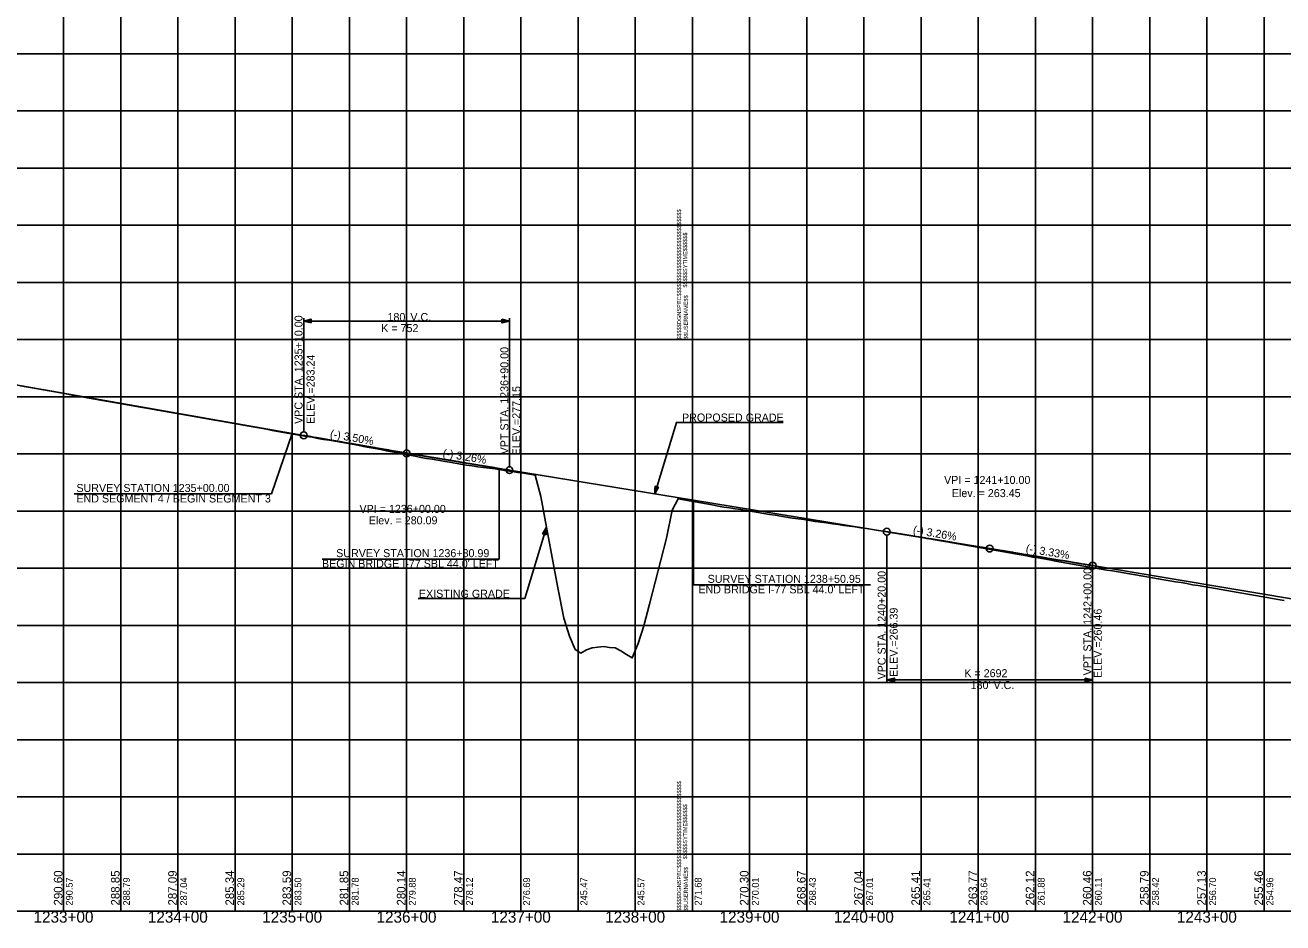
# Model space of a CAD drawing. Extents: x -90830 to 2015517, y -20856 to 836331.
# Drawn here: x 12190 to 13290, y -10807 to -10022 of the extents above; entities that cross this region are included whole.
import ezdxf

# ---------------------------------------------------------------- set-up
doc = ezdxf.new("R2010")
doc.units = 0
for name, color, linetype in [('Level 1', 7, 'Continuous'), ('RD_DDB_GradeTX', 7, 'Continuous'), ('RD_DDB_Profile_Elev', 7, 'Continuous'), ('RD_DDB_Profile_EX', 7, 'Continuous'), ('RD_DDB_Profile_Lbl', 7, 'Continuous'), ('RD_DDB_Profile_PR', 7, 'Continuous'), ('RD_DDB_StaTX', 7, 'Continuous'), ('RD_DDB_StripGrade', 7, 'Continuous'), ('RD_DDB_VCLbl', 7, 'Continuous'), ('RD_GPK_Profile_Cell', 7, 'Continuous'), ('RD_PD_Final_TX', 7, 'Continuous'), ('RD_TX_Drainage', 7, 'Continuous')]:
    doc.layers.add(name, color=color, linetype=linetype)

msp = doc.modelspace()

# ---------------------------------------------------------------- linework, layer by layer
at = {"layer": 'Level 1'}
for p, q in [((12223.5, -9797.1), (12223.5, -10297.1)), ((12273.5, -9797.1), (12273.5, -10297.1)), ((12323.5, -9797.1), (12323.5, -10297.1)), ((12373.5, -9797.1), (12373.5, -10297.1)), ((12423.5, -9797.1), (12423.5, -10297.1)), ((12473.5, -9797.1), (12473.5, -10297.1)), ((12523.5, -9797.1), (12523.5, -10297.1)), ((12573.5, -9797.1), (12573.5, -10297.1)), ((12623.5, -9797.1), (12623.5, -10297.1)), ((12673.5, -9797.1), (12673.5, -10297.1)), ((12723.5, -9797.1), (12723.5, -10297.1)), ((12773.5, -9797.1), (12773.5, -10297.1)), ((12773.5, -9797.1), (12773.5, -10297.1)), ((12773.5, -9797.1), (12773.5, -10297.1)), ((12823.5, -9797.1), (12823.5, -10297.1)), ((12873.5, -9797.1), (12873.5, -10297.1)), ((12923.5, -9797.1), (12923.5, -10297.1)), ((12973.5, -9797.1), (12973.5, -10297.1)), ((13023.5, -9797.1), (13023.5, -10297.1)), ((13073.5, -9797.1), (13073.5, -10297.1)), ((13123.5, -9797.1), (13123.5, -10297.1)), ((13173.5, -9797.1), (13173.5, -10297.1)), ((13223.5, -9797.1), (13223.5, -10297.1)), ((13273.5, -9797.1), (13273.5, -10297.1)), ((11173.5, -10047.1), (12773.5, -10047.1)), ((12773.5, -10047.1), (14373.5, -10047.1)), ((11173.5, -10097.1), (12773.5, -10097.1)), ((12773.5, -10097.1), (14373.5, -10097.1)), ((11173.5, -10147.1), (12773.5, -10147.1)), ((12773.5, -10147.1), (14373.5, -10147.1)), ((11173.5, -10197.1), (12773.5, -10197.1)), ((12773.5, -10197.1), (14373.5, -10197.1)), ((11173.5, -10247.1), (12773.5, -10247.1)), ((12773.5, -10247.1), (14373.5, -10247.1)), ((11173.5, -10297.1), (12773.5, -10297.1)), ((11173.5, -10297.1), (12773.5, -10297.1)), ((12223.5, -10297.1), (12223.5, -10797.1)), ((12273.5, -10297.1), (12273.5, -10797.1)), ((12323.5, -10297.1), (12323.5, -10797.1)), ((12373.5, -10297.1), (12373.5, -10797.1)), ((12423.5, -10297.1), (12423.5, -10797.1)), ((12473.5, -10297.1), (12473.5, -10797.1)), ((12523.5, -10297.1), (12523.5, -10797.1)), ((12573.5, -10297.1), (12573.5, -10797.1)), ((12623.5, -10297.1), (12623.5, -10797.1)), ((12673.5, -10297.1), (12673.5, -10797.1)), ((12723.5, -10297.1), (12723.5, -10797.1)), ((12773.5, -10297.1), (14373.5, -10297.1)), ((12773.5, -10297.1), (12773.5, -10797.1)), ((12773.5, -10297.1), (12773.5, -10797.1)), ((12773.5, -10297.1), (14373.5, -10297.1)), ((12773.5, -10297.1), (12773.5, -10797.1)), ((12823.5, -10297.1), (12823.5, -10797.1)), ((12873.5, -10297.1), (12873.5, -10797.1)), ((12923.5, -10297.1), (12923.5, -10797.1)), ((12973.5, -10297.1), (12973.5, -10797.1)), ((13023.5, -10297.1), (13023.5, -10797.1)), ((13073.5, -10297.1), (13073.5, -10797.1)), ((13123.5, -10297.1), (13123.5, -10797.1)), ((13173.5, -10297.1), (13173.5, -10797.1)), ((13223.5, -10297.1), (13223.5, -10797.1)), ((13273.5, -10297.1), (13273.5, -10797.1)), ((11173.5, -10347.1), (12773.5, -10347.1)), ((12773.5, -10347.1), (14373.5, -10347.1)), ((11173.5, -10397.1), (12773.5, -10397.1)), ((12773.5, -10397.1), (14373.5, -10397.1)), ((11173.5, -10447.1), (12773.5, -10447.1)), ((12773.5, -10447.1), (14373.5, -10447.1)), ((11173.5, -10497.1), (12773.5, -10497.1)), ((12773.5, -10497.1), (14373.5, -10497.1)), ((11173.5, -10547.1), (12773.5, -10547.1)), ((12773.5, -10547.1), (14373.5, -10547.1)), ((11173.5, -10597.1), (12773.5, -10597.1)), ((12773.5, -10597.1), (14373.5, -10597.1)), ((11173.5, -10647.1), (12773.5, -10647.1)), ((12773.5, -10647.1), (14373.5, -10647.1)), ((11173.5, -10697.1), (12773.5, -10697.1)), ((12773.5, -10697.1), (14373.5, -10697.1)), ((11173.5, -10747.1), (12773.5, -10747.1)), ((12773.5, -10747.1), (14373.5, -10747.1)), ((11173.5, -10797.1), (12773.5, -10797.1)), ((12773.5, -10797.1), (14373.5, -10797.1))]:
    msp.add_line(p, q, dxfattribs=at)
at = {"layer": 'RD_DDB_GradeTX'}
for p, q in [((12453.5, -10384.4), (12520.5, -10396.1)), ((12593.5, -10408.1), (12526.4, -10397.1)), ((12963.4, -10468.4), (13030.5, -10479.4)), ((13103.5, -10491.5), (13036.4, -10480.3))]:
    msp.add_line(p, q, dxfattribs=at)
for centre in [(12523.5, -10396.7), (13033.5, -10479.9)]:
    msp.add_circle(centre, 3, dxfattribs=at)
at = {"layer": 'RD_DDB_Profile_EX'}
for points in [[(12185.9, -10337.5), (12190.9, -10338.4), (12195.9, -10339.3), (12200.9, -10340.2), (12205.9, -10341.1), (12210.9, -10342), (12215.9, -10342.9), (12220.9, -10343.8), (12225.9, -10344.7), (12230.9, -10345.6), (12235.9, -10346.5), (12240.9, -10347.4), (12245.9, -10348.3), (12250.9, -10349.2), (12255.9, -10350.1), (12260.9, -10351), (12265.9, -10351.8), (12270.9, -10352.7), (12275.9, -10353.6), (12280.9, -10354.5), (12285.9, -10355.3), (12290.9, -10356.2), (12295.9, -10357.1), (12300.9, -10358), (12305.9, -10358.9), (12310.9, -10359.7), (12315.9, -10360.6), (12320.9, -10361.5), (12325.9, -10362.3), (12330.9, -10363.2), (12335.9, -10364.1), (12340.9, -10364.9), (12345.9, -10365.8), (12350.9, -10366.7), (12355.9, -10367.5), (12360.9, -10368.4), (12365.9, -10369.3), (12370.9, -10370.2), (12375.9, -10371.1), (12380.9, -10372), (12385.9, -10372.9), (12390.9, -10373.8), (12395.9, -10374.7), (12400.9, -10375.6), (12405.9, -10376.5), (12410.9, -10377.4), (12415.9, -10378.3), (12420.9, -10379.2), (12425.9, -10380), (12430.9, -10380.9), (12435.9, -10381.8), (12440.9, -10382.6), (12445.9, -10383.5), (12450.9, -10384.4), (12455.9, -10385.2), (12460.9, -10386.1), (12465.9, -10386.9), (12470.9, -10387.8), (12475.9, -10388.7), (12480.9, -10389.6), (12485.9, -10390.5), (12490.9, -10391.4), (12495.9, -10392.3), (12500.9, -10393.3), (12505.9, -10394.3), (12510.9, -10395.3), (12515.9, -10396.3), (12520.9, -10397.2), (12525.9, -10398.2), (12530.9, -10399.2), (12535.9, -10400.2), (12540.9, -10401), (12545.9, -10401.8)], [(12545.9, -10401.8), (12550.9, -10402.7), (12555.9, -10403.5), (12560.9, -10404.3), (12565.9, -10405.2), (12570.9, -10406.1), (12575.9, -10406.9), (12580.9, -10407.6), (12585.9, -10408.3), (12590.9, -10409), (12595.9, -10409.7), (12600.9, -10410.3), (12605.9, -10411), (12610.9, -10411.8), (12615.9, -10412.5), (12620.9, -10413.3), (12625.9, -10414.1), (12630.9, -10414.9), (12635.9, -10415.7), (12640.9, -10434.5), (12645.9, -10461.2), (12650.9, -10487.8), (12655.9, -10514.3), (12660.9, -10540.8), (12665.9, -10556.6), (12670.9, -10568.3), (12675.9, -10571.3), (12680.9, -10568.5), (12685.9, -10566.6), (12690.9, -10566.1), (12695.9, -10565.7), (12700.9, -10566.3), (12705.9, -10566.8), (12710.9, -10569.4), (12715.9, -10572.5), (12720.9, -10575.6), (12725.9, -10562.9), (12730.9, -10547.5), (12735.9, -10528.4), (12740.9, -10509.2), (12745.9, -10490.1), (12750.9, -10470.9), (12755.9, -10446.4), (12760.9, -10436.5), (12765.9, -10437.4), (12770.9, -10438.3), (12775.9, -10439.1), (12780.9, -10440), (12785.9, -10440.9), (12790.9, -10441.8), (12795.9, -10442.8), (12800.9, -10443.6), (12805.9, -10444.3), (12810.9, -10445.1), (12815.9, -10445.8), (12820.9, -10446.6), (12825.9, -10447.5), (12830.9, -10448.3), (12835.9, -10449.2), (12840.9, -10450), (12845.9, -10450.8), (12850.9, -10451.6), (12855.9, -10452.4), (12860.9, -10453.2), (12865.9, -10453.9), (12870.9, -10454.6), (12875.9, -10455.4), (12880.9, -10456.1), (12885.9, -10456.8), (12890.9, -10457.5), (12895.9, -10458.2), (12900.9, -10458.9), (12905.9, -10459.6), (12910.9, -10460.3), (12915.9, -10461), (12920.9, -10461.7), (12925.9, -10462.5), (12930.9, -10463.2), (12935.9, -10464), (12940.9, -10464.7), (12945.9, -10465.5), (12950.9, -10466.3), (12955.9, -10467.1), (12960.9, -10467.9), (12965.9, -10468.8), (12970.9, -10469.6), (12975.9, -10470.5), (12980.9, -10471.4), (12985.9, -10472.2), (12990.9, -10473.1), (12995.9, -10474), (13000.9, -10474.9), (13005.9, -10475.8), (13010.9, -10476.7), (13015.9, -10477.6), (13020.9, -10478.5), (13025.9, -10479.4), (13030.9, -10480.2), (13035.9, -10481.1), (13040.9, -10482), (13045.9, -10482.9)], [(13045.9, -10482.9), (13050.9, -10483.7), (13055.9, -10484.6), (13060.9, -10485.5), (13065.9, -10486.4), (13070.9, -10487.3), (13075.9, -10488.1), (13080.9, -10489), (13085.9, -10489.9), (13090.9, -10490.8), (13095.9, -10491.7), (13100.9, -10492.6), (13105.9, -10493.5), (13110.9, -10494.4), (13115.9, -10495.3), (13120.9, -10496.1), (13125.9, -10497), (13130.9, -10497.8), (13135.9, -10498.7), (13140.9, -10499.5), (13145.9, -10500.4), (13150.9, -10501.2), (13155.9, -10502), (13160.9, -10502.9), (13165.9, -10503.8), (13170.9, -10504.6), (13175.9, -10505.5), (13180.9, -10506.3), (13185.9, -10507.2), (13190.9, -10508), (13195.9, -10508.9), (13200.9, -10509.7), (13205.9, -10510.6), (13210.9, -10511.5), (13215.9, -10512.3), (13220.9, -10513.2), (13225.9, -10514.1), (13230.9, -10514.9), (13235.9, -10515.8), (13240.9, -10516.7), (13245.9, -10517.6), (13250.9, -10518.4), (13255.9, -10519.3), (13260.9, -10520.2), (13265.9, -10521), (13270.9, -10521.9), (13275.9, -10522.7), (13280.9, -10523.6), (13285.9, -10524.4), (13290.9, -10525.2)]]:
    msp.add_lwpolyline(points, dxfattribs=at)
at = {"layer": 'RD_DDB_Profile_Lbl'}
for p, q in [((12423.5, -10379.2), (12405.2, -10432.1)), ((12604.4, -10489.3), (12604.4, -10409.9)), ((12232.7, -10432.1), (12405.2, -10432.1)), ((12774.4, -10511.5), (12774.4, -10437.6)), ((12449.8, -10489.3), (12604.4, -10489.3)), ((12774.4, -10511.5), (12929.1, -10511.5))]:
    msp.add_line(p, q, dxfattribs=at)
at = {"layer": 'RD_DDB_Profile_PR'}
for p, q in [((11473.4, -10212.8), (12433.5, -10380.9)), ((12613.5, -10411.3), (12774.4, -10437.6)), ((12774.4, -10437.6), (12943.5, -10465.2)), ((13123.5, -10494.8), (13336, -10530.2))]:
    msp.add_line(p, q, dxfattribs=at)
for points in [[(12433.5, -10380.9), (12437.1, -10381.5), (12440.7, -10382.2), (12444.3, -10382.8), (12447.9, -10383.4), (12451.5, -10384), (12455.1, -10384.7), (12458.7, -10385.3), (12462.3, -10385.9), (12465.9, -10386.5), (12469.5, -10387.2), (12473.1, -10387.8), (12476.7, -10388.4), (12480.3, -10389), (12483.9, -10389.6), (12487.5, -10390.3), (12491.1, -10390.9), (12494.7, -10391.5), (12498.3, -10392.1), (12501.9, -10392.7), (12505.5, -10393.3), (12509.1, -10394), (12512.7, -10394.6), (12516.3, -10395.2), (12519.9, -10395.8), (12523.5, -10396.4), (12527.1, -10397), (12530.7, -10397.6), (12534.3, -10398.2), (12537.9, -10398.8), (12541.5, -10399.4), (12545.1, -10400), (12548.7, -10400.6), (12552.3, -10401.2), (12555.9, -10401.8), (12559.5, -10402.4), (12563.1, -10403), (12566.7, -10403.6), (12570.3, -10404.2), (12573.9, -10404.8), (12577.5, -10405.4), (12581.1, -10406), (12584.7, -10406.6), (12588.3, -10407.2), (12591.9, -10407.8), (12595.5, -10408.4), (12599.1, -10409), (12602.7, -10409.6), (12604.4, -10409.9)], [(12604.4, -10409.9), (12606.3, -10410.2), (12609.9, -10410.8), (12613.5, -10411.3)], [(12943.5, -10465.2), (12947.1, -10465.8), (12950.7, -10466.4), (12954.3, -10466.9), (12957.9, -10467.5), (12961.5, -10468.1), (12965.1, -10468.7), (12968.7, -10469.3), (12972.3, -10469.9), (12975.9, -10470.5), (12979.5, -10471.1), (12983.1, -10471.6), (12986.7, -10472.2), (12990.3, -10472.8), (12993.9, -10473.4), (12997.5, -10474), (13001.1, -10474.6), (13004.7, -10475.2), (13008.3, -10475.8), (13011.9, -10476.4), (13015.5, -10477), (13019.1, -10477.6), (13022.7, -10478.2), (13026.3, -10478.7), (13029.9, -10479.3), (13033.5, -10479.9), (13037.1, -10480.5), (13040.7, -10481.1), (13044.3, -10481.7), (13047.9, -10482.3), (13051.5, -10482.9), (13055.1, -10483.5), (13058.7, -10484.1), (13062.3, -10484.7), (13065.9, -10485.3), (13069.5, -10485.9), (13073.1, -10486.5), (13076.7, -10487.1), (13080.3, -10487.7), (13083.9, -10488.3), (13087.5, -10488.9), (13091.1, -10489.5), (13094.7, -10490.1), (13098.3, -10490.6), (13101.9, -10491.2), (13105.5, -10491.8), (13109.1, -10492.4), (13112.7, -10493), (13116.3, -10493.6), (13119.9, -10494.2), (13123.5, -10494.8)]]:
    msp.add_spline(points, degree=3, dxfattribs=at)
at = {"layer": 'RD_DDB_VCLbl'}
for p, q in [((12433.5, -10278.4), (12433.5, -10377.9)), ((12433.5, -10280.9), (12613.5, -10280.9)), ((12613.5, -10278.4), (12613.5, -10408.3)), ((12943.5, -10597.3), (12943.5, -10468.2)), ((13123.5, -10597.3), (13123.5, -10497.8)), ((12943.5, -10594.8), (13123.5, -10594.8))]:
    msp.add_line(p, q, dxfattribs=at)
for centre in [(12433.5, -10380.9), (12613.5, -10411.3), (12943.5, -10465.2), (13123.5, -10494.8)]:
    msp.add_circle(centre, 3, dxfattribs=at)
at = {"layer": 'RD_GPK_Profile_Cell'}
msp.add_line((4823.5, -10797.1), (75223.5, -10797.1), dxfattribs=at)
at = {"layer": 'RD_PD_Final_TX'}
for p, q in [((12740.5, -10432), (12740.8, -10425.3)), ((12742.3, -10425.8), (12740.5, -10432)), ((12740.5, -10432), (12743.9, -10426.3)), ((12740.8, -10425.3), (12743.9, -10426.3)), ((12645.9, -10461.2), (12642.5, -10466.9)), ((12645.6, -10467.8), (12642.5, -10466.9)), ((12644.1, -10467.4), (12645.9, -10461.2)), ((12645.9, -10461.2), (12645.6, -10467.8))]:
    msp.add_line(p, q, dxfattribs=at)
for points in [[(12852.9, -10369.6), (12759.5, -10369.6), (12740.5, -10432)], [(12742.3, -10425.9), (12740.5, -10431.6), (12742.3, -10425.8), (12740.5, -10431.4), (12742.2, -10425.8), (12740.6, -10431.2), (12742.1, -10425.8), (12740.6, -10430.9), (12742, -10425.8), (12740.6, -10430.6), (12742, -10425.7), (12740.6, -10430.2), (12741.9, -10425.7), (12740.6, -10429.9), (12741.8, -10425.7), (12740.6, -10429.6), (12741.7, -10425.7), (12740.7, -10429.3), (12741.7, -10425.7), (12740.7, -10429), (12741.6, -10425.7), (12740.7, -10428.7), (12741.5, -10425.6), (12740.7, -10428.2), (12741.4, -10425.6), (12740.7, -10427.9), (12741.4, -10425.6), (12740.7, -10427.5), (12741.3, -10425.6), (12740.8, -10427.1), (12741.2, -10425.5), (12740.8, -10426.8), (12741.1, -10425.5), (12740.8, -10426.5), (12741.1, -10425.4), (12740.8, -10426.1), (12741, -10425.5), (12740.8, -10425.7), (12740.9, -10425.5)], [(12740.6, -10431.6), (12742.4, -10425.9), (12740.7, -10431.4), (12742.4, -10425.9), (12740.8, -10431.2), (12742.5, -10425.9), (12740.9, -10431.1), (12742.6, -10425.9), (12741.1, -10430.9), (12742.6, -10425.9), (12741.2, -10430.7), (12742.7, -10426), (12741.3, -10430.5), (12742.7, -10426), (12741.5, -10430.2), (12742.8, -10426), (12741.6, -10429.9), (12742.9, -10426), (12741.8, -10429.7), (12742.9, -10426), (12741.9, -10429.5), (12743, -10426), (12742.1, -10429.2), (12743, -10426.1), (12742.3, -10428.9), (12743.1, -10426.1), (12742.4, -10428.6), (12743.2, -10426.1), (12742.6, -10428.3), (12743.2, -10426.1), (12742.8, -10428), (12743.3, -10426.2), (12742.9, -10427.8), (12743.4, -10426.2), (12743.1, -10427.6), (12743.4, -10426.2), (12743.2, -10427.2), (12743.5, -10426.2), (12743.4, -10427), (12743.6, -10426.3), (12743.5, -10426.9), (12743.7, -10426.3), (12743.8, -10426.3), (12743.7, -10426.3)], [(12533.5, -10523.5), (12626.9, -10523.5), (12645.9, -10461.2)], [(12645.8, -10461.5), (12644, -10467.3), (12645.7, -10461.7), (12644, -10467.2), (12645.6, -10461.9), (12643.9, -10467.3), (12645.5, -10462.1), (12643.9, -10467.2), (12645.3, -10462.3), (12643.8, -10467.2), (12645.2, -10462.5), (12643.7, -10467.2), (12645.1, -10462.7), (12643.7, -10467.2), (12644.9, -10463), (12643.6, -10467.2), (12644.8, -10463.2), (12643.5, -10467.2), (12644.7, -10463.5), (12643.5, -10467.1), (12644.5, -10463.7), (12643.4, -10467.1), (12644.3, -10464), (12643.4, -10467.1), (12644.1, -10464.3), (12643.3, -10467.1), (12644, -10464.5), (12643.2, -10467.1), (12643.8, -10464.8), (12643.2, -10467), (12643.7, -10465.1), (12643.1, -10467), (12643.5, -10465.4), (12643, -10466.9), (12643.3, -10465.6), (12643, -10466.9), (12643.2, -10465.9), (12642.9, -10466.9), (12643.1, -10466.1), (12642.8, -10466.9), (12642.9, -10466.3), (12642.7, -10466.8), (12642.6, -10466.9), (12642.7, -10466.8)], [(12644.1, -10467.3), (12645.9, -10461.5), (12644.2, -10467.3), (12645.9, -10461.8), (12644.2, -10467.3), (12645.9, -10462), (12644.3, -10467.3), (12645.9, -10462.2), (12644.4, -10467.4), (12645.8, -10462.6), (12644.5, -10467.4), (12645.8, -10463), (12644.5, -10467.4), (12645.8, -10463.3), (12644.6, -10467.5), (12645.8, -10463.6), (12644.7, -10467.4), (12645.7, -10463.9), (12644.7, -10467.5), (12645.7, -10464.1), (12644.8, -10467.5), (12645.7, -10464.5), (12644.9, -10467.5), (12645.7, -10464.9), (12645, -10467.6), (12645.7, -10465.2), (12645, -10467.6), (12645.7, -10465.7), (12645.1, -10467.6), (12645.6, -10466.1), (12645.2, -10467.7), (12645.6, -10466.4), (12645.3, -10467.7), (12645.6, -10466.7), (12645.3, -10467.7), (12645.6, -10467), (12645.4, -10467.7), (12645.6, -10467.4), (12645.5, -10467.7)]]:
    msp.add_lwpolyline(points, dxfattribs=at)
at = {"layer": 'RD_TX_Drainage'}
for points in [[(12440.1, -10282.6), (12433.5, -10280.9), (12440.1, -10279.3)], [(12606.9, -10279.3), (12613.5, -10280.9), (12606.9, -10282.6)], [(12950.1, -10596.5), (12943.5, -10594.8), (12950.1, -10593.2)], [(13116.9, -10593.2), (13123.5, -10594.8), (13116.9, -10596.5)]]:
    msp.add_lwpolyline(points, close=True, dxfattribs=at)

# ---------------------------------------------------------------- texts
at = {"layer": 'Level 1'}
for s, p in [('$$$$$DGNSPEC$$$$$$$$$$$$$$$$$$$$$$$$$$$$', (12763.6, -10297.2)), ('$$$$$SYTIME$$$$$$', (12768.9, -10251.6)), ('$$USERNAME$$', (12769.5, -10297)), ('$$$$$DGNSPEC$$$$$$$$$$$$$$$$$$$$$$$$$$$$', (12763.6, -10797.2)), ('$$$$$SYTIME$$$$$$', (12768.9, -10751.6)), ('$$USERNAME$$', (12769.5, -10797))]:
    msp.add_text(s, height=3.544, rotation=90, dxfattribs=at).set_placement(p)
at = {"layer": 'RD_DDB_GradeTX'}
for s, rotation, p in [('(-) 3.50%', 350.069, (12456.1, -10382.8)), ('(-) 3.26%', 350.7353, (12554.7, -10399.7)), ('(-) 3.26%', 350.7353, (12966, -10466.8)), ('(-) 3.33%', 350.5488, (13064.7, -10483))]:
    msp.add_text(s, height=7, rotation=rotation, dxfattribs=at).set_placement(p)
at = {"layer": 'RD_DDB_Profile_Elev'}
for s, p in [('290.60', (12222.5, -10792.1)), ('288.85', (12272.5, -10792.1)), ('287.09', (12322.5, -10792.1)), ('285.34', (12372.5, -10792.1)), ('283.59', (12422.5, -10792.1)), ('281.85', (12472.5, -10792.1)), ('280.14', (12522.5, -10792.1)), ('278.47', (12572.5, -10792.1)), ('270.30', (12822.5, -10792.1)), ('268.67', (12872.5, -10792.1)), ('267.04', (12922.5, -10792.1)), ('265.41', (12972.5, -10792.1)), ('263.77', (13022.5, -10792.1)), ('262.12', (13072.5, -10792.1)), ('260.46', (13122.5, -10792.1)), ('258.79', (13172.5, -10792.1)), ('257.13', (13222.5, -10792.1)), ('255.46', (13272.5, -10792.1))]:
    msp.add_text(s, height=7.5, rotation=90, dxfattribs=at).set_placement(p)
at = {"layer": 'RD_DDB_Profile_Lbl'}
for s, p in [('VPI = 1241+10.00', (12993.6, -10423.4)), ('SURVEY STATION 1235+00.00', (12234.7, -10430.4)), ('Elev. = 263.45', (13000.4, -10434.9)), ('END SEGMENT 4 / BEGIN SEGMENT 3', (12234.7, -10439.6)), ('VPI = 1236+00.00', (12482.3, -10448.7)), ('Elev. = 280.09', (12490.4, -10458.7)), ('SURVEY STATION 1236+80.99', (12461.9, -10487.4)), ("BEGIN BRIDGE I-77 SBL 44.0' LEFT", (12449.5, -10496.6)), ('SURVEY STATION 1238+50.95', (12786.8, -10509.9)), ("END BRIDGE I-77 SBL 44.0' LEFT", (12778.7, -10519.1))]:
    msp.add_text(s, height=7, dxfattribs=at).set_placement(p)
at = {"layer": 'RD_DDB_StaTX'}
for s, p in [('1233+00', (12197.2, -10807.1)), ('1234+00', (12297.2, -10807.1)), ('1235+00', (12397.2, -10807.1)), ('1236+00', (12497.2, -10807.1)), ('1237+00', (12597.2, -10807.1)), ('1238+00', (12697.2, -10807.1)), ('1239+00', (12797.2, -10807.1)), ('1240+00', (12897.2, -10807.1)), ('1241+00', (12998.2, -10807.1)), ('1242+00', (13097.2, -10807.1)), ('1243+00', (13197.2, -10807.1))]:
    msp.add_text(s, height=10, dxfattribs=at).set_placement(p)
at = {"layer": 'RD_DDB_StripGrade'}
for s, height, p in [('VPC STA. 1235+10.00 ', 7, (12432.5, -10370.9)), (' VPT STA. 1236+90.00 ', 7, (12612.5, -10400.1)), ('ELEV.=283.24', 7, (12443, -10370.9)), ('ELEV.=277.15', 7, (12623, -10398.4)), ('VPC STA. 1240+20.00 ', 7, (12942.5, -10594.4)), (' VPT STA. 1242+00.00 ', 7, (13122.5, -10593.4)), ('ELEV.=266.39', 7, (12953, -10592.2)), ('ELEV.=260.46', 7, (13131.5, -10593.1)), ('290.57', 6, (12231.5, -10792.1)), ('288.79', 6, (12281.5, -10792.1)), ('287.04', 6, (12331.5, -10792.1)), ('285.29', 6, (12381.5, -10792.1)), ('283.50', 6, (12431.5, -10792.1)), ('281.78', 6, (12481.5, -10792.1)), ('279.88', 6, (12531.5, -10792.1)), ('278.12', 6, (12581.5, -10792.1)), ('276.69', 6, (12631.5, -10792.1)), ('245.47', 6, (12681.5, -10792.1)), ('245.57', 6, (12731.5, -10792.1)), ('271.68', 6, (12781.5, -10792.1)), ('270.01', 6, (12831.5, -10792.1)), ('268.43', 6, (12881.5, -10792.1)), ('267.01', 6, (12931.5, -10792.1)), ('265.41', 6, (12981.5, -10792.1)), ('263.64', 6, (13031.5, -10792.1)), ('261.88', 6, (13081.5, -10792.1)), ('260.11', 6, (13131.5, -10792.1)), ('258.42', 6, (13181.5, -10792.1)), ('256.70', 6, (13231.5, -10792.1)), ('254.96', 6, (13281.5, -10792.1))]:
    msp.add_text(s, height=height, rotation=90, dxfattribs=at).set_placement(p)
at = {"layer": 'RD_DDB_VCLbl'}
for s, p in [("180' V.C.", (12506.8, -10280.9)), ('K = 752', (12501.3, -10290.6)), ('K = 2692', (13011.3, -10592.4)), ("180' V.C.", (13016.8, -10602.8))]:
    msp.add_text(s, height=7, dxfattribs=at).set_placement(p)
at = {"layer": 'RD_PD_Final_TX'}
for s, p in [('PROPOSED GRADE', (12764.4, -10368.8)), ('EXISTING GRADE', (12534.3, -10522.9))]:
    msp.add_text(s, height=7, dxfattribs=at).set_placement(p)

doc.saveas('drawing.dxf')
